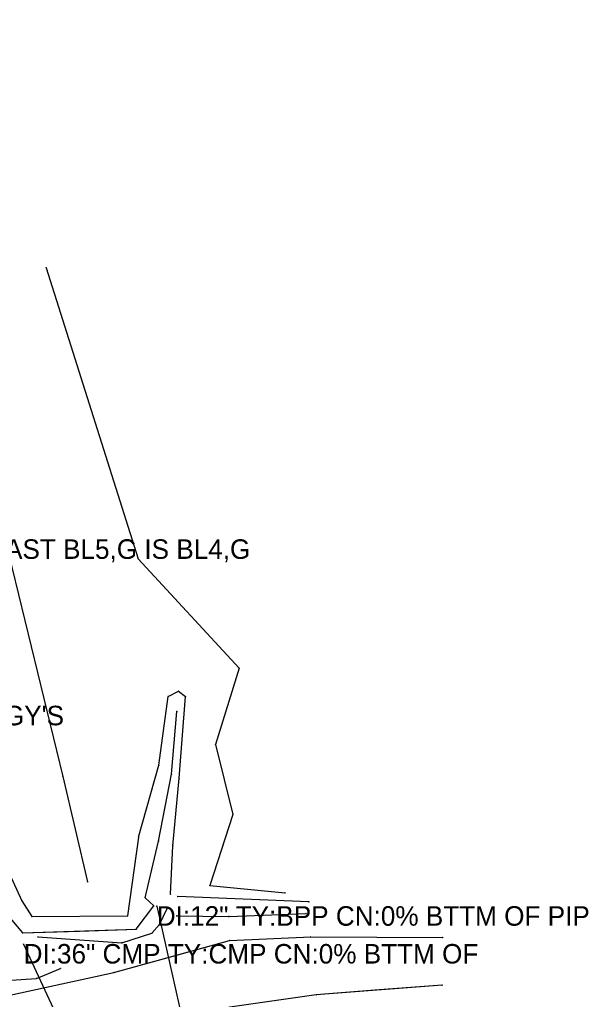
# Model space of a CAD drawing. Extents: x -99999 to 591807, y -99999 to 347168.
# Drawn here: x 588601.2 to 588746.8, y 345924.7 to 346175.5 of the extents above; entities that cross this region are included whole.
import ezdxf

# ---------------------------------------------------------------- set-up
doc = ezdxf.new("R2010")
doc.units = 0
for name, color, linetype in [('S_BREAKLINE', 7, 'Continuous'), ('S_DITCHLINE', 7, 'Continuous'), ('S_DRG_PT_SYM', 7, 'Continuous'), ('S_DRIVEWAY', 7, 'Continuous'), ('S_FENCE_ANNOT', 7, 'Continuous'), ('S_GRD_PT_SYM', 7, 'Continuous'), ('S_RDW_PT_SYM', 7, 'Continuous'), ('S_SIDE_DRAIN', 7, 'Continuous'), ('S_SIDE_DRAIN_ANNOT', 7, 'Continuous'), ('S_UTILITY_POLE_ANNOT', 7, 'Continuous')]:
    doc.layers.add(name, color=color, linetype=linetype)

msp = doc.modelspace()

# ---------------------------------------------------------------- linework, layer by layer
at = {"layer": 'S_BREAKLINE'}
for points in [[(588607.96, 346111.98), (588631.54, 346037.48), (588657.35, 346009.48), (588651.32, 345989.95), (588655.77, 345972.01), (588649.84, 345953.88), (588669.13, 345951.96)], [(588597.64, 346041.68), (588612.19, 345981.73), (588618.52, 345954.76)], [(588631.64, 345966.23), (588636.8, 345984.63), (588639.16, 346002.18), (588641.86, 346003.57), (588643.6, 346002.24)], [(588639.83, 345951.61), (588640.37, 345964.03), (588642.04, 345981.29), (588643.6, 346002.24)], [(588589.95, 345975.44), (588601.77, 345949.95)], [(588631.64, 345966.23), (588628.79, 345946.06)], [(588601.77, 345949.95), (588604.3, 345945.93)], [(588627.34, 345939.16), (588635.03, 345941.61), (588637.01, 345943.83), (588638.83, 345947.8)], [(588641.42, 345946.08), (588654.73, 345945.89), (588674.49, 345946.64)], [(588604.3, 345945.93), (588628.79, 345946.06)], [(588605.84, 345940.68), (588627.34, 345939.16)]]:
    msp.add_lwpolyline(points, dxfattribs=at)
at = {"layer": 'S_DITCHLINE'}
for points in [[(588257.35, 346289.25), (588280.5, 346271.3), (588311.42, 346243.03), (588335.92, 346217.96), (588365.97, 346190.07), (588375.97, 346178.27), (588390.65, 346166.99), (588416.36, 346140.22), (588445.78, 346111.15), (588483.3, 346075.52), (588519.2, 346042.05), (588548.23, 346010.87), (588571.04, 345986.23), (588581.12, 345970.7), (588597.81, 345946.58), (588601.9, 345941.76), (588631.02, 345942.63), (588635.56, 345948.64), (588633.33, 345950.72), (588636.71, 345965.2), (588640.07, 345982.32), (588641.42, 345998.38)], [(588597.81, 345946.58), (588601.9, 345941.76), (588616.46, 345942.19), (588631.02, 345942.63), (588635.56, 345948.64), (588633.33, 345950.72), (588636.71, 345965.2), (588640.07, 345982.32), (588641.42, 345998.38)], [(588675.22, 345949.64), (588641.66, 345951.03)], [(588675.22, 345949.64), (588658.44, 345950.34), (588641.66, 345951.03)], [(588709.33, 345928.34), (588677.1, 345925.89), (588654.98, 345922.74), (588642.19, 345919.41), (588626.18, 345914.06), (588613.83, 345907.69), (588605.68, 345896.3), (588601.18, 345883.72)], [(588709.33, 345928.34), (588693.22, 345927.12), (588677.1, 345925.89), (588654.98, 345922.74), (588642.19, 345919.41), (588626.18, 345914.06), (588613.83, 345907.69), (588605.68, 345896.3), (588601.18, 345883.72)]]:
    msp.add_lwpolyline(points, dxfattribs=at)
at = {"layer": 'S_DRG_PT_SYM'}
for points in [[(588636.28, 345948.55), (588636.28, 345948.6), (588636.28, 345948.55), (588636.23, 345948.55), (588636.28, 345948.55), (588636.28, 345948.5), (588636.28, 345948.55), (588636.33, 345948.55)], [(588602.19, 345938.87), (588602.19, 345938.92), (588602.19, 345938.87), (588602.14, 345938.87), (588602.19, 345938.87), (588602.19, 345938.82), (588602.19, 345938.87), (588602.24, 345938.87)]]:
    msp.add_lwpolyline(points, dxfattribs=at)
at = {"layer": 'S_DRIVEWAY'}
for points in [[(588534.21, 346003.78), (588556.97, 345973.94), (588562.32, 345964.45), (588577.19, 345940.02), (588596.39, 345929.45), (588605.45, 345930), (588611.61, 345932.62)], [(588534.21, 346003.78), (588545.59, 345988.86), (588556.97, 345973.94), (588562.32, 345964.45), (588569.75, 345952.24), (588577.19, 345940.02), (588596.39, 345929.45), (588605.45, 345930), (588611.61, 345932.62)], [(588577.61, 345931.56), (588581.9, 345931.62), (588594.66, 345924.91), (588625.32, 345931.56), (588654.88, 345939.75), (588675.7, 345940.69), (588709.49, 345940.57)], [(588577.61, 345931.56), (588581.9, 345931.62), (588594.66, 345924.91), (588609.99, 345928.24), (588625.32, 345931.56), (588640.1, 345935.66), (588654.88, 345939.75), (588675.7, 345940.69), (588692.59, 345940.63), (588709.49, 345940.57)]]:
    msp.add_lwpolyline(points, dxfattribs=at)
at = {"layer": 'S_GRD_PT_SYM'}
for points in [[(588607.96, 346111.98), (588608.01, 346112), (588607.96, 346111.98), (588607.94, 346112.03), (588607.96, 346111.98), (588607.91, 346111.97), (588607.96, 346111.98), (588607.97, 346111.94)], [(588631.54, 346037.48), (588631.58, 346037.52), (588631.54, 346037.48), (588631.51, 346037.52), (588631.54, 346037.48), (588631.51, 346037.45), (588631.54, 346037.48), (588631.58, 346037.45)], [(588657.35, 346009.48), (588657.39, 346009.47), (588657.35, 346009.48), (588657.36, 346009.53), (588657.35, 346009.48), (588657.3, 346009.5), (588657.35, 346009.48), (588657.33, 346009.44)], [(588639.16, 346002.18), (588639.14, 346002.22), (588639.16, 346002.18), (588639.11, 346002.16), (588639.16, 346002.18), (588639.18, 346002.13), (588639.16, 346002.18), (588639.2, 346002.2)], [(588641.86, 346003.57), (588641.89, 346003.61), (588641.86, 346003.57), (588641.82, 346003.6), (588641.86, 346003.57), (588641.83, 346003.53), (588641.86, 346003.57), (588641.9, 346003.54)], [(588643.6, 346002.24), (588643.55, 346002.25), (588643.6, 346002.24), (588643.59, 346002.19), (588643.6, 346002.24), (588643.65, 346002.24), (588643.6, 346002.24), (588643.6, 346002.29)], [(588643.6, 346002.24), (588643.63, 346002.28), (588643.6, 346002.24), (588643.56, 346002.27), (588643.6, 346002.24), (588643.57, 346002.2), (588643.6, 346002.24), (588643.64, 346002.21)], [(588641.42, 345998.38), (588641.37, 345998.38), (588641.42, 345998.38), (588641.42, 345998.33), (588641.42, 345998.38), (588641.47, 345998.37), (588641.42, 345998.38), (588641.43, 345998.43)], [(588651.32, 345989.95), (588651.37, 345989.97), (588651.32, 345989.95), (588651.31, 345990), (588651.32, 345989.95), (588651.27, 345989.94), (588651.32, 345989.95), (588651.33, 345989.9)], [(588636.8, 345984.63), (588636.76, 345984.64), (588636.8, 345984.63), (588636.8, 345984.58), (588636.8, 345984.63), (588636.85, 345984.63), (588636.8, 345984.63), (588636.81, 345984.68)], [(588612.19, 345981.73), (588612.24, 345981.75), (588612.19, 345981.73), (588612.18, 345981.78), (588612.19, 345981.73), (588612.15, 345981.72), (588612.19, 345981.73), (588612.21, 345981.69)], [(588640.07, 345982.32), (588640.02, 345982.32), (588640.07, 345982.32), (588640.06, 345982.27), (588640.07, 345982.32), (588640.12, 345982.31), (588640.07, 345982.32), (588640.07, 345982.37)], [(588642.04, 345981.29), (588641.99, 345981.29), (588642.04, 345981.29), (588642.04, 345981.24), (588642.04, 345981.29), (588642.09, 345981.29), (588642.04, 345981.29), (588642.05, 345981.34)], [(588655.77, 345972.01), (588655.81, 345971.99), (588655.77, 345972.01), (588655.78, 345972.05), (588655.77, 345972.01), (588655.72, 345972.02), (588655.77, 345972.01), (588655.75, 345971.96)], [(588631.64, 345966.23), (588631.69, 345966.23), (588631.64, 345966.23), (588631.65, 345966.28), (588631.64, 345966.23), (588631.59, 345966.24), (588631.64, 345966.23), (588631.63, 345966.18)], [(588631.64, 345966.23), (588631.59, 345966.25), (588631.64, 345966.23), (588631.62, 345966.18), (588631.64, 345966.23), (588631.69, 345966.22), (588631.64, 345966.23), (588631.65, 345966.28)], [(588636.71, 345965.2), (588636.66, 345965.21), (588636.71, 345965.2), (588636.7, 345965.15), (588636.71, 345965.2), (588636.76, 345965.19), (588636.71, 345965.2), (588636.72, 345965.24)], [(588640.37, 345964.03), (588640.32, 345964.03), (588640.37, 345964.03), (588640.36, 345963.98), (588640.37, 345964.03), (588640.42, 345964.02), (588640.37, 345964.03), (588640.37, 345964.08)], [(588618.52, 345954.76), (588618.57, 345954.77), (588618.52, 345954.76), (588618.51, 345954.8), (588618.52, 345954.76), (588618.47, 345954.74), (588618.52, 345954.76), (588618.53, 345954.71)], [(588649.84, 345953.88), (588649.85, 345953.93), (588649.84, 345953.88), (588649.79, 345953.89), (588649.84, 345953.88), (588649.84, 345953.83), (588649.84, 345953.88), (588649.89, 345953.88)], [(588639.83, 345951.61), (588639.78, 345951.62), (588639.83, 345951.61), (588639.83, 345951.56), (588639.83, 345951.61), (588639.88, 345951.61), (588639.83, 345951.61), (588639.83, 345951.66)], [(588669.13, 345951.96), (588669.14, 345952.01), (588669.13, 345951.96), (588669.08, 345951.96), (588669.13, 345951.96), (588669.13, 345951.91), (588669.13, 345951.96), (588669.18, 345951.95)], [(588601.77, 345949.95), (588601.82, 345949.97), (588601.77, 345949.95), (588601.75, 345950), (588601.77, 345949.95), (588601.73, 345949.93), (588601.77, 345949.95), (588601.79, 345949.9)], [(588601.77, 345949.95), (588601.82, 345949.98), (588601.77, 345949.95), (588601.75, 345949.99), (588601.77, 345949.95), (588601.73, 345949.92), (588601.77, 345949.95), (588601.8, 345949.91)], [(588633.33, 345950.72), (588633.28, 345950.74), (588633.33, 345950.72), (588633.32, 345950.68), (588633.33, 345950.72), (588633.38, 345950.71), (588633.33, 345950.72), (588633.34, 345950.77)], [(588641.66, 345951.03), (588641.66, 345950.98), (588641.66, 345951.03), (588641.71, 345951.03), (588641.66, 345951.03), (588641.66, 345951.08), (588641.66, 345951.03), (588641.61, 345951.03)], [(588675.22, 345949.64), (588675.21, 345949.59), (588675.22, 345949.64), (588675.27, 345949.64), (588675.22, 345949.64), (588675.22, 345949.69), (588675.22, 345949.64), (588675.17, 345949.64)], [(588635.56, 345948.64), (588635.53, 345948.6), (588635.56, 345948.64), (588635.6, 345948.61), (588635.56, 345948.64), (588635.59, 345948.68), (588635.56, 345948.64), (588635.52, 345948.67)], [(588638.83, 345947.8), (588638.79, 345947.82), (588638.83, 345947.8), (588638.81, 345947.76), (588638.83, 345947.8), (588638.88, 345947.78), (588638.83, 345947.8), (588638.85, 345947.85)], [(588674.49, 345946.64), (588674.49, 345946.69), (588674.49, 345946.64), (588674.44, 345946.64), (588674.49, 345946.64), (588674.49, 345946.59), (588674.49, 345946.64), (588674.54, 345946.65)], [(588604.3, 345945.93), (588604.34, 345945.96), (588604.3, 345945.93), (588604.27, 345945.98), (588604.3, 345945.93), (588604.25, 345945.91), (588604.3, 345945.93), (588604.32, 345945.89)], [(588604.3, 345945.93), (588604.3, 345945.98), (588604.3, 345945.93), (588604.25, 345945.93), (588604.3, 345945.93), (588604.3, 345945.88), (588604.3, 345945.93), (588604.35, 345945.93)], [(588628.79, 345946.06), (588628.84, 345946.05), (588628.79, 345946.06), (588628.8, 345946.11), (588628.79, 345946.06), (588628.74, 345946.06), (588628.79, 345946.06), (588628.78, 345946.01)], [(588628.79, 345946.06), (588628.79, 345946.11), (588628.79, 345946.06), (588628.74, 345946.06), (588628.79, 345946.06), (588628.79, 345946.01), (588628.79, 345946.06), (588628.84, 345946.06)], [(588628.79, 345946.06), (588628.79, 345946.11), (588628.79, 345946.06), (588628.74, 345946.06), (588628.79, 345946.06), (588628.79, 345946.01), (588628.79, 345946.06), (588628.84, 345946.06)], [(588641.42, 345946.08), (588641.42, 345946.13), (588641.42, 345946.08), (588641.37, 345946.08), (588641.42, 345946.08), (588641.42, 345946.03), (588641.42, 345946.08), (588641.47, 345946.08)], [(588654.73, 345945.89), (588654.73, 345945.94), (588654.73, 345945.89), (588654.68, 345945.89), (588654.73, 345945.89), (588654.73, 345945.84), (588654.73, 345945.89), (588654.78, 345945.89)], [(588601.9, 345941.76), (588601.9, 345941.81), (588601.9, 345941.76), (588601.85, 345941.76), (588601.9, 345941.76), (588601.9, 345941.71), (588601.9, 345941.76), (588601.95, 345941.77)], [(588631.02, 345942.63), (588630.98, 345942.66), (588631.02, 345942.63), (588630.99, 345942.59), (588631.02, 345942.63), (588631.06, 345942.6), (588631.02, 345942.63), (588631.05, 345942.67)], [(588635.03, 345941.61), (588634.99, 345941.64), (588635.03, 345941.61), (588634.99, 345941.57), (588635.03, 345941.61), (588635.06, 345941.58), (588635.03, 345941.61), (588635.06, 345941.65)], [(588637.01, 345943.83), (588636.97, 345943.85), (588637.01, 345943.83), (588636.99, 345943.79), (588637.01, 345943.83), (588637.06, 345943.81), (588637.01, 345943.83), (588637.03, 345943.88)], [(588605.84, 345940.68), (588605.85, 345940.73), (588605.84, 345940.68), (588605.79, 345940.69), (588605.84, 345940.68), (588605.84, 345940.63), (588605.84, 345940.68), (588605.89, 345940.68)], [(588605.84, 345940.68), (588605.84, 345940.73), (588605.84, 345940.68), (588605.79, 345940.68), (588605.84, 345940.68), (588605.84, 345940.63), (588605.84, 345940.68), (588605.89, 345940.68)], [(588627.34, 345939.16), (588627.35, 345939.21), (588627.34, 345939.16), (588627.29, 345939.16), (588627.34, 345939.16), (588627.34, 345939.11), (588627.34, 345939.16), (588627.39, 345939.16)], [(588627.34, 345939.16), (588627.33, 345939.21), (588627.34, 345939.16), (588627.3, 345939.15), (588627.34, 345939.16), (588627.36, 345939.11), (588627.34, 345939.16), (588627.39, 345939.18)], [(588611.61, 345932.62), (588611.61, 345932.67), (588611.61, 345932.62), (588611.56, 345932.62), (588611.61, 345932.62), (588611.61, 345932.57), (588611.61, 345932.62), (588611.66, 345932.62)], [(588605.45, 345930), (588605.45, 345930.05), (588605.45, 345930), (588605.4, 345930), (588605.45, 345930), (588605.45, 345929.95), (588605.45, 345930), (588605.5, 345930)], [(588709.33, 345928.34), (588709.34, 345928.29), (588709.33, 345928.34), (588709.38, 345928.35), (588709.33, 345928.34), (588709.33, 345928.39), (588709.33, 345928.34), (588709.28, 345928.34)], [(588677.1, 345925.89), (588677.11, 345925.84), (588677.1, 345925.89), (588677.15, 345925.89), (588677.1, 345925.89), (588677.09, 345925.94), (588677.1, 345925.89), (588677.05, 345925.88)]]:
    msp.add_lwpolyline(points, close=True, dxfattribs=at)
at = {"layer": 'S_RDW_PT_SYM'}
for points in [[(588654.88, 345939.75), (588654.88, 345939.8), (588654.88, 345939.75), (588654.83, 345939.75), (588654.88, 345939.75), (588654.88, 345939.7), (588654.88, 345939.75), (588654.93, 345939.75)], [(588675.7, 345940.69), (588675.7, 345940.74), (588675.7, 345940.69), (588675.65, 345940.69), (588675.7, 345940.69), (588675.7, 345940.64), (588675.7, 345940.69), (588675.75, 345940.69)], [(588709.49, 345940.57), (588709.49, 345940.62), (588709.49, 345940.57), (588709.44, 345940.57), (588709.49, 345940.57), (588709.49, 345940.52), (588709.49, 345940.57), (588709.54, 345940.57)], [(588611.61, 345932.62), (588611.59, 345932.66), (588611.61, 345932.62), (588611.56, 345932.6), (588611.61, 345932.62), (588611.63, 345932.57), (588611.61, 345932.62), (588611.65, 345932.64)], [(588625.32, 345931.56), (588625.31, 345931.61), (588625.32, 345931.56), (588625.28, 345931.55), (588625.32, 345931.56), (588625.34, 345931.51), (588625.32, 345931.56), (588625.37, 345931.58)], [(588605.45, 345930), (588605.43, 345930.04), (588605.45, 345930), (588605.41, 345929.98), (588605.45, 345930), (588605.47, 345929.95), (588605.45, 345930), (588605.5, 345930.02)], [(588709.33, 345928.34), (588709.33, 345928.39), (588709.33, 345928.34), (588709.28, 345928.34), (588709.33, 345928.34), (588709.33, 345928.29), (588709.33, 345928.34), (588709.38, 345928.34)], [(588677.1, 345925.89), (588677.1, 345925.94), (588677.1, 345925.89), (588677.05, 345925.89), (588677.1, 345925.89), (588677.1, 345925.84), (588677.1, 345925.89), (588677.15, 345925.89)]]:
    msp.add_lwpolyline(points, close=True, dxfattribs=at)
at = {"layer": 'S_SIDE_DRAIN'}
for p, q in [((588636.28, 345948.55), (588645.03, 345909.74)), ((588602.19, 345938.87), (588622.55, 345894.77))]:
    msp.add_line(p, q, dxfattribs=at)

# ---------------------------------------------------------------- texts
at = {"layer": 'S_FENCE_ANNOT'}
msp.add_text('LAST BL5,G IS BL4,G', height=5, dxfattribs=at).set_placement((588593.71, 346037.45))
at = {"layer": 'S_SIDE_DRAIN_ANNOT'}
for s, p in [('DI:12" TY:BPP CN:0% BTTM OF PIP', (588636.28, 345943.55)), ('DI:36" CMP TY:CMP CN:0% BTTM OF', (588602.19, 345933.87))]:
    msp.add_text(s, height=5, dxfattribs=at).set_placement(p)
at = {"layer": 'S_UTILITY_POLE_ANNOT'}
msp.add_text("2 GY'S", height=5, dxfattribs=at).set_placement((588591.57, 345994.85))

doc.saveas('drawing.dxf')
